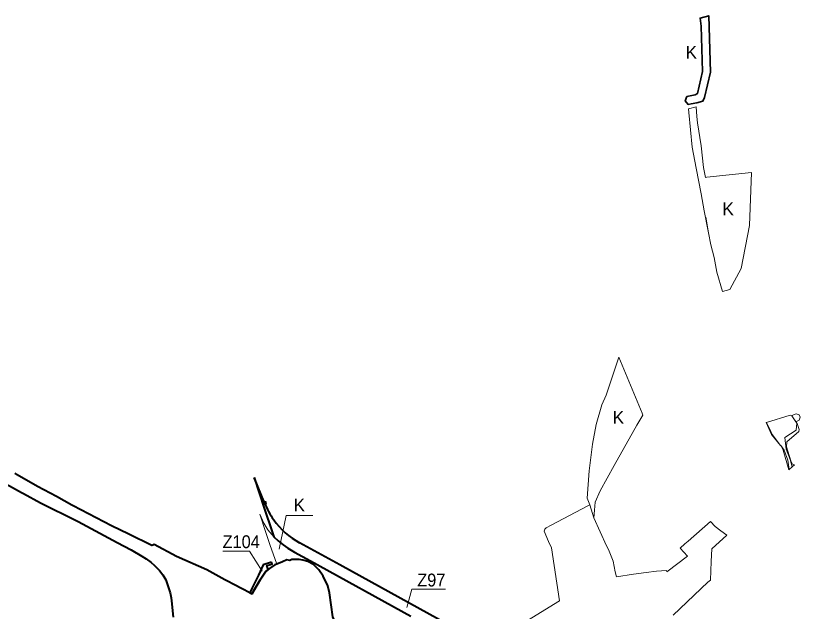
# Model space of a CAD drawing. Extents: x -650276 to -642489, y -1074425 to -1066658.
# Drawn here: x -647044 to -645579, y -1068604 to -1067493 of the extents above; entities that cross this region are included whole.
import ezdxf

# ---------------------------------------------------------------- set-up
doc = ezdxf.new("R2010")
doc.units = 0
doc.header["$LTSCALE"] = 9.6
doc.header["$PDMODE"] = 32
doc.header["$PDSIZE"] = 4.8
for name, color, linetype, lineweight in [('1', 7, 'Continuous', 13), ('43', 7, 'Continuous', 13), ('44', 7, 'Continuous', 40), ('45', 7, 'Continuous', 40), ('46', 7, 'Continuous', 13), ('47', 7, 'Continuous', 13), ('5', 7, 'Continuous', 35)]:
    doc.layers.add(name, color=color, linetype=linetype, lineweight=lineweight)

msp = doc.modelspace()

# ---------------------------------------------------------------- linework, layer by layer
at = {"layer": '1'}
for p, q in [((-645587.06, -1068250.38), (-645580.9, -1068247.49)), ((-645600.44, -1068340.02), (-645599.575, -1068339.279))]:
    msp.add_line(p, q, dxfattribs=at)
for points in [[(-645585.534, -1068252.628), (-645594.58, -1068239.29), (-645597.95, -1068238.07), (-645641.935, -1068251.454)], [(-645580.9, -1068247.49), (-645578.75, -1068241.63), (-645580.62, -1068237.58), (-645586.3, -1068235.27), (-645594.36, -1068238.9), (-645594.58, -1068239.29), (-645587.059, -1068250.379), (-645587.06, -1068250.38)], [(-645641.935, -1068251.454), (-645642.71, -1068251.69), (-645632.7, -1068274.33)], [(-645641.935, -1068251.454), (-645636.48, -1068262.88), (-645631.15, -1068274.06), (-645615.786, -1068294.399)], [(-645632.7, -1068274.33), (-645615.786, -1068294.399), (-645631.15, -1068274.06), (-645636.48, -1068262.88), (-645641.935, -1068251.454)], [(-645585.534, -1068252.628), (-645586.19, -1068266.26), (-645607.95, -1068279.56), (-645605.1, -1068301.42)], [(-645605.1, -1068301.42), (-645607.95, -1068279.56), (-645586.19, -1068266.26), (-645585.534, -1068252.628)], [(-645593.644, -1068334.201), (-645589.73, -1068330.85), (-645593.42, -1068329.62), (-645596.36, -1068323.47), (-645604.65, -1068297.22), (-645603.62, -1068287.78), (-645581.51, -1068268.4), (-645580.86, -1068265.06), (-645584.8, -1068253.71), (-645585.534, -1068252.628)], [(-645615.786, -1068294.399), (-645615.49, -1068294.75), (-645615.41, -1068294.897), (-645609.13, -1068303.21)], [(-645599.6, -1068339.25), (-645602.09, -1068321.99), (-645609.13, -1068303.21), (-645615.41, -1068294.897)], [(-645615.41, -1068294.897), (-645610.72, -1068303.48), (-645600.44, -1068340.02)], [(-645609.13, -1068303.21), (-645602.09, -1068321.99), (-645599.6, -1068339.25)], [(-645605.1, -1068301.42), (-645597.41, -1068320.95), (-645593.644, -1068334.201)], [(-645599.575, -1068339.279), (-645593.644, -1068334.201), (-645597.41, -1068320.95), (-645605.1, -1068301.42)], [(-645816.02, -1068611.01), (-645751.23, -1068549.94), (-645746.63, -1068545.61), (-645745.39, -1068511.09), (-645744.06, -1068487.4), (-645716.22, -1068462.08), (-645727.32, -1068453.86), (-645737.89, -1068446.04), (-645746.68, -1068436.15), (-645788.09, -1068473.04), (-645794.06, -1068478.36), (-645803.01, -1068486.33), (-645789.58, -1068501.42), (-645827.73, -1068530.12), (-645828.52, -1068527.64), (-645847.4, -1068528.93), (-645866.58, -1068531.3), (-645890.02, -1068534.9), (-645922.02, -1068539.96), (-645924.25, -1068530.17), (-645927.86, -1068510.76), (-645936.95, -1068488.76), (-645940.28, -1068481.66), (-645964.53, -1068429.83), (-645971.94, -1068405.38), (-645975.47, -1068407.25), (-646043.93, -1068443.44), (-646053.26, -1068448.37), (-646055.56, -1068450.55), (-646056.77, -1068454.35), (-646048.96, -1068473.76), (-646043.13, -1068485.53), (-646028.19, -1068584.65), (-646136.66, -1068651.17)]]:
    msp.add_lwpolyline(points, dxfattribs=at)
at = {"layer": '43'}
msp.add_lwpolyline([(-646488.64, -1068425), (-646538.869, -1068425), (-646552.014, -1068487.951)], dxfattribs=at)
msp.add_lwpolyline([(-646488.64, -1068425), (-646538.869, -1068425), (-646552.014, -1068487.951)], dxfattribs=at)
at = {"layer": '44'}
msp.add_line((-646578.881, -1068401.54), (-646598.635, -1068354.436), dxfattribs=at)
for points in [[(-647419.713, -1068138.871), (-647405.71, -1068151.74), (-647372.38, -1068179.01), (-647337.74, -1068205.67), (-647334.62, -1068208.02), (-647307.39, -1068227.44), (-647281.64, -1068244.34), (-647234.11, -1068273.04), (-647230.83, -1068274.93), (-647174.56, -1068306.35), (-647142.788, -1068322.462), (-647130.29, -1068328.8), (-647079.16, -1068357.01), (-647032.91, -1068382.51), (-647029.23, -1068384.46), (-646997.06, -1068401.37), (-646929.56, -1068435.42), (-646927.06, -1068436.66)], [(-646545.57, -1068511.42), (-646556.22, -1068515.84), (-646559.72, -1068517.29), (-646569.61, -1068524.1), (-646572.02, -1068526.07), (-646577.07, -1068530.2), (-646587.28, -1068545.28), (-646599.75, -1068566.49), (-646602.21, -1068571.5), (-646606.59, -1068569.33), (-646620.94, -1068561.96), (-646625.86, -1068559.47), (-646631.18, -1068556.77), (-646653.21, -1068545.58), (-646686.84, -1068526.89), (-646686.84, -1068526.89), (-646743.69, -1068501.76), (-646785.05, -1068479.12), (-646787.55, -1068480.36), (-646789.49, -1068481.31), (-646832.29, -1068460.04), (-646864.48, -1068444.64), (-646936.47, -1068407.23), (-646938.95, -1068405.8), (-646967.64, -1068390), (-647002.71, -1068371.09), (-647040.77, -1068349.4), (-647044.93, -1068347.08)], [(-646598.635, -1068354.436), (-646579.62, -1068411.29), (-646564.78, -1068455.41), (-646561.544, -1068464.842)], [(-646927.06, -1068436.66), (-646854.18, -1068475.8), (-646828.2, -1068489.61), (-646807.82, -1068501.17), (-646799.79, -1068506.39), (-646790.66, -1068513.24), (-646785.34, -1068517.77), (-646779.93, -1068522.9), (-646775.44, -1068527.74), (-646768.95, -1068535.8), (-646763.1, -1068545.18), (-646754.92, -1068569.81), (-646753.35, -1068578.6), (-646752.59, -1068584.55), (-646749.35, -1068615.18)], [(-646561.544, -1068464.842), (-646553.677, -1068472.283), (-646544.525, -1068479.79), (-646535.245, -1068486.342), (-646523.105, -1068493.54), (-646493.511, -1068509.855), (-646305.678, -1068613.404)], [(-646234.342, -1068629.893), (-646234.342, -1068629.892), (-646438.626, -1068517.274), (-646513.45, -1068476.025), (-646513.567, -1068475.963)], [(-646337.93, -1068712.4), (-646404.83, -1068671.52), (-646413.45, -1068664.71), (-646422.32, -1068655.58), (-646425.11, -1068652.37), (-646446.54, -1068626.14), (-646451.82, -1068614.31), (-646458.03, -1068569.26), (-646461.14, -1068556.34), (-646469.51, -1068538.15), (-646477.41, -1068526.45), (-646487.92, -1068516.87), (-646498.48, -1068511.26), (-646507.4, -1068508.45), (-646514.39, -1068507.56), (-646528.18, -1068507.58), (-646531.9, -1068509.25), (-646537.71, -1068508.16), (-646545.57, -1068511.42)]]:
    msp.add_lwpolyline(points, dxfattribs=at)
at = {"layer": '44', "lineweight": 13}
msp.add_lwpolyline([(-646241.379, -1068562.947), (-646303.746, -1068562.947), (-646313.477, -1068597.03)], dxfattribs=at)
msp.add_lwpolyline([(-646241.379, -1068562.947), (-646303.746, -1068562.947), (-646313.477, -1068597.03)], dxfattribs=at)
at = {"layer": '44'}
for start, end in [(200.6496, 215.36619), (215.36631, 241.891)]:
    msp.add_arc((-646447.332, -1068351.964), 140.58, start, end, dxfattribs=at)
msp.add_point((-646578.881, -1068401.54), dxfattribs=at)
at = {"layer": '45'}
for points in [[(-646566.33, -1068512.04), (-646581.64, -1068517.24), (-646590.31, -1068536.69), (-646602.01, -1068560.15), (-646606.59, -1068569.33)], [(-646566.33, -1068512.04), (-646581.64, -1068517.24), (-646590.31, -1068536.69), (-646602.01, -1068560.15), (-646606.59, -1068569.33)], [(-646587.28, -1068545.28), (-646577.07, -1068530.2), (-646572.02, -1068526.07), (-646574.48, -1068518.75), (-646565.04, -1068515.86), (-646566.33, -1068512.04)], [(-646587.28, -1068545.28), (-646577.07, -1068530.2), (-646572.02, -1068526.07), (-646574.48, -1068518.75), (-646565.04, -1068515.86), (-646566.33, -1068512.04)], [(-646599.75, -1068566.49), (-646587.28, -1068545.28), (-646587.28, -1068545.28)], [(-646599.75, -1068566.49), (-646587.28, -1068545.28), (-646587.28, -1068545.28)], [(-646606.59, -1068569.33), (-646602.21, -1068571.5), (-646599.75, -1068566.49)], [(-646606.59, -1068569.33), (-646602.21, -1068571.5), (-646599.75, -1068566.49)]]:
    msp.add_lwpolyline(points, dxfattribs=at)
at = {"layer": '46'}
msp.add_lwpolyline([(-646656.853, -1068492.089), (-646606.877, -1068492.089), (-646583.419, -1068529.344)], dxfattribs=at)
msp.add_lwpolyline([(-646656.853, -1068492.089), (-646606.877, -1068492.089), (-646583.419, -1068529.344)], dxfattribs=at)
at = {"layer": '47'}
for points in [[(-645751.08, -1067894.5), (-645755.058, -1067868.324), (-645750.41, -1067897.81), (-645745.86, -1067920.32), (-645739.85, -1067943.75), (-645734.61, -1067971.28), (-645723.79, -1068007.07), (-645710.519, -1068003.601), (-645688.88, -1067964.087), (-645673.827, -1067884.119), (-645670.064, -1067785.335), (-645753.14, -1067793.982), (-645755.758, -1067794.254), (-645759.32, -1067775.89), (-645763.92, -1067735.14), (-645770.39, -1067692.63), (-645771.86, -1067680.92), (-645773.23, -1067662.67), (-645787.55, -1067666.46), (-645787.165, -1067673.232), (-645780.39, -1067737.84), (-645773.04, -1067777.35), (-645773.04, -1067777.35), (-645764.11, -1067825.26), (-645758.47, -1067856.55)], [(-645874.15, -1068234.44), (-645917.44, -1068129.99), (-645938.87, -1068193.06), (-645941.41, -1068200.54), (-645949.52, -1068218.72), (-645959.76, -1068255.23), (-645966.56, -1068292.38), (-645973.25, -1068342.08), (-645976.63, -1068393.14), (-645971.94, -1068405.38), (-645964.53, -1068429.83), (-645963.12, -1068415.21), (-645961.7, -1068400.54), (-645952.21, -1068378.95), (-645926.06, -1068332.18), (-645883.87, -1068256.88), (-645880.28, -1068250.47), (-645872.64, -1068238.08)]]:
    msp.add_lwpolyline(points, close=True, dxfattribs=at)
for points in [[(-646561.544, -1068464.842), (-646572.984, -1068451.81), (-646580.625, -1068439.803), (-646588.07, -1068422.96), (-646576.4, -1068457.27), (-646568.87, -1068479.14), (-646556.22, -1068515.84), (-646545.57, -1068511.42), (-646537.71, -1068508.16)], [(-646523.105, -1068493.54), (-646535.245, -1068486.342), (-646544.525, -1068479.79), (-646553.677, -1068472.283), (-646561.544, -1068464.842)], [(-646537.71, -1068508.16), (-646531.9, -1068509.25), (-646528.18, -1068507.58), (-646514.39, -1068507.56), (-646507.4, -1068508.45), (-646498.48, -1068511.26), (-646495.416, -1068512.888), (-646493.511, -1068509.855), (-646523.105, -1068493.54)]]:
    msp.add_lwpolyline(points, dxfattribs=at)
at = {"layer": '5'}
for points in [[(-645757.79, -1067645.206), (-645746.448, -1067597.944), (-645749.67, -1067492.54), (-645765.859, -1067496.872), (-645764.084, -1067511.925), (-645761.499, -1067596.501), (-645770.809, -1067637.786), (-645775.114, -1067640.43), (-645790.381, -1067643.17)], [(-645790.381, -1067643.17), (-645793.94, -1067651.61), (-645788.395, -1067658.038), (-645782.72, -1067657.28), (-645772.13, -1067655.13), (-645760.67, -1067652.05), (-645757.79, -1067645.206)]]:
    msp.add_lwpolyline(points, dxfattribs=at)

# ---------------------------------------------------------------- texts
at = {"layer": '43'}
for p in [(-645792.887, -1067572.893), (-645724.189, -1067865.057), (-645724.189, -1067865.057), (-645928.983, -1068254.123), (-645928.983, -1068254.123), (-646524.8, -1068417.662), (-646524.8, -1068417.662)]:
    msp.add_text('K', height=24, dxfattribs=at).set_placement(p)
at = {"layer": '44', "width": 0.95}
msp.add_text('Z97', height=24, dxfattribs=at).set_placement((-646293.907, -1068557.715))
msp.add_text('Z97', height=24, dxfattribs=at).set_placement((-646293.907, -1068557.715))
at = {"layer": '46', "width": 0.95}
msp.add_text('Z104', height=24, dxfattribs=at).set_placement((-646657.338, -1068486.184))
msp.add_text('Z104', height=24, dxfattribs=at).set_placement((-646657.338, -1068486.184))

doc.saveas('drawing.dxf')
